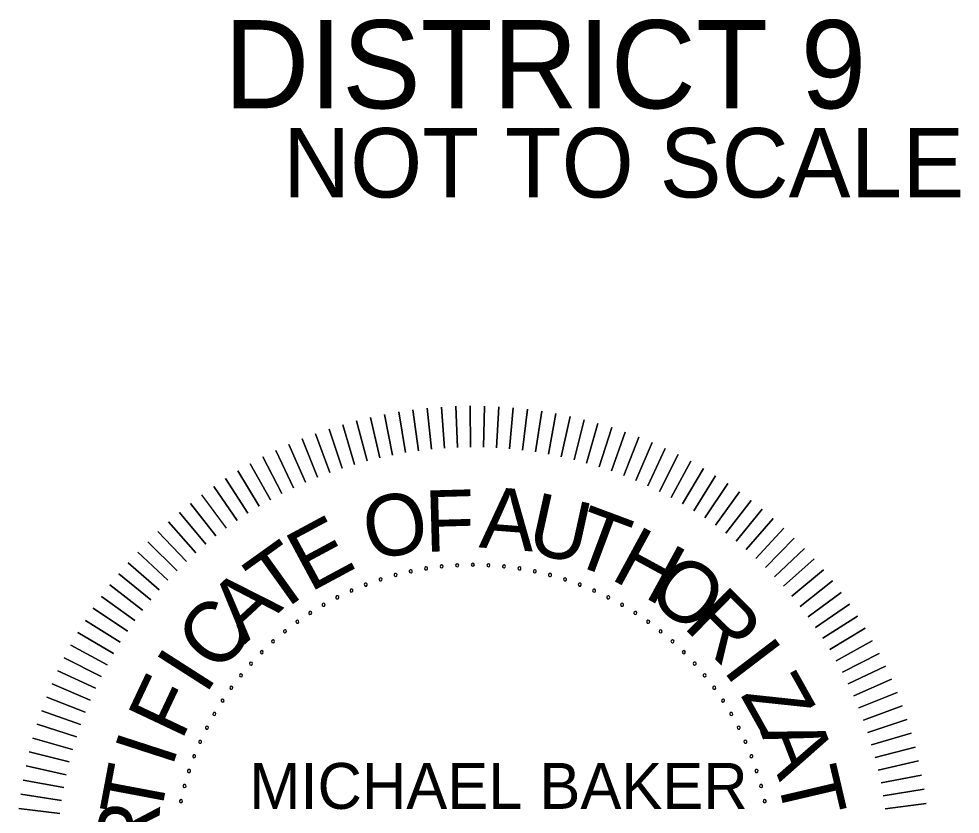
# Model space of a CAD drawing. Extents: x -13171 to 18763, y -8840 to 11152.
# Drawn here: x 10556 to 13118, y -7462 to -5298 of the extents above; entities that cross this region are included whole.
import ezdxf

# ---------------------------------------------------------------- set-up
doc = ezdxf.new("R2010")
doc.units = 0
for name, color, linetype in [('Level 2', 7, 'Continuous'), ('Level 47', 7, 'Continuous'), ('Level 48', 7, 'Continuous')]:
    doc.layers.add(name, color=color, linetype=linetype)

msp = doc.modelspace()

# ---------------------------------------------------------------- linework, layer by layer
at = {"layer": 'Level 47'}
for points in [[(11750, -6464.1), (11745.9, -6351.9)], [(11745.9, -6351.9), (11750, -6464.1)], [(11785.6, -6463.3), (11785, -6351.1)], [(11785, -6351.1), (11785.6, -6463.3)], [(11821.1, -6463.7), (11824, -6351.5)], [(11824, -6351.5), (11821.1, -6463.7)], [(11856.7, -6465.2), (11863.1, -6353.1)], [(11863.1, -6353.1), (11856.7, -6465.2)], [(11573.5, -6484.6), (11551.9, -6374.4)], [(11551.9, -6374.4), (11573.5, -6484.6)], [(11608.5, -6478.2), (11590.4, -6367.5)], [(11590.4, -6367.5), (11608.5, -6478.2)], [(11643.7, -6473), (11629, -6361.8)], [(11629, -6361.8), (11643.7, -6473)], [(11679.1, -6468.9), (11667.9, -6357.3)], [(11667.9, -6357.3), (11679.1, -6468.9)], [(11714.5, -6466), (11706.8, -6354)], [(11706.8, -6354), (11714.5, -6466)], [(11892.2, -6467.8), (11902.1, -6356)], [(11902.1, -6356), (11892.2, -6467.8)], [(11927.5, -6471.5), (11941, -6360)], [(11941, -6360), (11927.5, -6471.5)], [(11962.8, -6476.3), (11979.7, -6365.3)], [(11979.7, -6365.3), (11962.8, -6476.3)], [(11997.8, -6482.2), (12018.3, -6371.8)], [(12018.3, -6371.8), (11997.8, -6482.2)], [(11470, -6510), (11438.1, -6402.4)], [(11438.1, -6402.4), (11470, -6510)], [(11504.2, -6500.5), (11475.7, -6391.9)], [(11475.7, -6391.9), (11504.2, -6500.5)], [(11538.8, -6492), (11513.7, -6382.6)], [(11513.7, -6382.6), (11538.8, -6492)], [(12032.7, -6489.2), (12056.6, -6379.6)], [(12056.6, -6379.6), (12032.7, -6489.2)], [(12067.3, -6497.3), (12094.6, -6388.5)], [(12094.6, -6388.5), (12067.3, -6497.3)], [(12101.7, -6506.5), (12132.4, -6398.6)], [(12132.4, -6398.6), (12101.7, -6506.5)], [(11402.4, -6532.4), (11363.8, -6427)], [(11363.8, -6427), (11402.4, -6532.4)], [(11436, -6520.7), (11400.8, -6414.1)], [(11400.8, -6414.1), (11436, -6520.7)], [(12135.7, -6516.8), (12169.8, -6409.9)], [(12169.8, -6409.9), (12135.7, -6516.8)], [(12169.5, -6528.1), (12206.9, -6422.3)], [(12206.9, -6422.3), (12169.5, -6528.1)], [(11369.2, -6545.2), (11327.4, -6441)], [(11327.4, -6441), (11369.2, -6545.2)], [(12202.8, -6540.5), (12243.5, -6435.9)], [(12243.5, -6435.9), (12202.8, -6540.5)], [(12235.7, -6553.9), (12279.7, -6450.7)], [(12279.7, -6450.7), (12235.7, -6553.9)], [(11304.1, -6573.8), (11255.8, -6472.5)], [(11255.8, -6472.5), (11304.1, -6573.8)], [(11336.5, -6558.9), (11291.3, -6456.2)], [(11291.3, -6456.2), (11336.5, -6558.9)], [(12268.2, -6568.4), (12315.5, -6466.6)], [(12315.5, -6466.6), (12268.2, -6568.4)], [(11272.3, -6589.6), (11220.8, -6489.9)], [(11220.8, -6489.9), (11272.3, -6589.6)], [(12300.3, -6583.9), (12350.7, -6483.6)], [(12350.7, -6483.6), (12300.3, -6583.9)], [(12331.8, -6600.3), (12385.3, -6501.7)], [(12385.3, -6501.7), (12331.8, -6600.3)], [(11210.1, -6624.2), (11152.5, -6527.9)], [(11152.5, -6527.9), (11210.1, -6624.2)], [(11240.9, -6606.4), (11186.3, -6508.4)], [(11186.3, -6508.4), (11240.9, -6606.4)], [(12362.8, -6617.8), (12419.4, -6520.9)], [(12419.4, -6520.9), (12362.8, -6617.8)], [(11179.9, -6643), (11119.3, -6548.5)], [(11119.3, -6548.5), (11179.9, -6643)], [(12393.2, -6636.2), (12452.8, -6541.1)], [(12452.8, -6541.1), (12393.2, -6636.2)], [(11150.3, -6662.6), (11086.7, -6570.2)], [(11086.7, -6570.2), (11150.3, -6662.6)], [(12423, -6655.6), (12485.6, -6562.4)], [(12485.6, -6562.4), (12423, -6655.6)], [(11121.3, -6683.3), (11054.8, -6592.8)], [(12452.3, -6675.8), (12517.7, -6584.7)], [(12517.7, -6584.7), (12452.3, -6675.8)], [(12480.8, -6697), (12549.1, -6608)], [(12549.1, -6608), (12480.8, -6697)], [(11093, -6704.8), (11023.7, -6616.5)], [(11023.7, -6616.5), (11093, -6704.8)], [(12508.7, -6719.1), (12579.8, -6632.3)], [(12579.8, -6632.3), (12508.7, -6719.1)], [(11065.4, -6727.2), (10993.3, -6641.1)], [(10993.3, -6641.1), (11065.4, -6727.2)], [(12535.9, -6742.1), (12609.6, -6657.5)], [(12609.6, -6657.5), (12535.9, -6742.1)], [(11038.4, -6750.4), (10963.8, -6666.6)], [(10963.8, -6666.6), (11038.4, -6750.4)], [(12638.7, -6683.6), (12562.3, -6765.9)], [(12562.3, -6765.9), (12638.7, -6683.6)], [(11012.3, -6774.5), (10935, -6693.1)], [(10935, -6693.1), (11012.3, -6774.5)], [(12666.9, -6710.7), (12588, -6790.5)], [(12588, -6790.5), (12666.9, -6710.7)], [(10986.9, -6799.4), (10907.1, -6720.5)], [(10907.1, -6720.5), (10986.9, -6799.4)], [(10962.3, -6825.1), (10880, -6748.7)], [(10880, -6748.7), (10962.3, -6825.1)], [(12694.3, -6738.6), (12612.9, -6815.9)], [(12612.9, -6815.9), (12694.3, -6738.6)], [(10938.5, -6851.5), (10853.9, -6777.8)], [(10853.9, -6777.8), (10938.5, -6851.5)], [(12720.7, -6767.4), (12637, -6842)], [(12637, -6842), (12720.7, -6767.4)], [(10915.5, -6878.7), (10828.6, -6807.6)], [(10828.6, -6807.6), (10915.5, -6878.7)], [(12746.3, -6796.9), (12660.2, -6869)], [(12660.2, -6869), (12746.3, -6796.9)], [(10893.4, -6906.6), (10804.4, -6838.3)], [(10804.4, -6838.3), (10893.4, -6906.6)], [(12770.9, -6827.3), (12682.6, -6896.6)], [(12682.6, -6896.6), (12770.9, -6827.3)], [(12794.5, -6858.4), (12704.1, -6924.9)], [(12704.1, -6924.9), (12794.5, -6858.4)], [(10872.2, -6935.1), (10781.1, -6869.7)], [(10781.1, -6869.7), (10872.2, -6935.1)], [(12817.2, -6890.3), (12724.7, -6953.9)], [(12724.7, -6953.9), (12817.2, -6890.3)], [(10851.9, -6964.3), (10758.8, -6901.8)], [(10758.8, -6901.8), (10851.9, -6964.3)], [(10832.6, -6994.2), (10737.5, -6934.6)], [(10737.5, -6934.6), (10832.6, -6994.2)], [(12838.9, -6922.9), (12744.4, -6983.5)], [(12744.4, -6983.5), (12838.9, -6922.9)], [(10814.2, -7024.6), (10717.3, -6968)], [(10717.3, -6968), (10814.2, -7024.6)], [(12859.5, -6956.1), (12763.2, -7013.7)], [(12763.2, -7013.7), (12859.5, -6956.1)], [(12879, -6989.9), (12781, -7044.5)], [(12781, -7044.5), (12879, -6989.9)], [(10796.7, -7055.6), (10698.1, -7002.1)], [(10698.1, -7002.1), (10796.7, -7055.6)], [(10780.3, -7087.1), (10680, -7036.7)], [(10680, -7036.7), (10780.3, -7087.1)], [(12897.5, -7024.4), (12797.8, -7075.9)], [(12797.8, -7075.9), (12897.5, -7024.4)], [(12914.9, -7059.4), (12813.6, -7107.7)], [(12813.6, -7107.7), (12914.9, -7059.4)], [(10764.8, -7119.1), (10663, -7071.9)], [(10663, -7071.9), (10764.8, -7119.1)], [(12931.2, -7094.9), (12828.4, -7140.1)], [(12828.4, -7140.1), (12931.2, -7094.9)], [(10750.3, -7151.6), (10647.1, -7107.6)], [(10647.1, -7107.6), (10750.3, -7151.6)], [(10736.9, -7184.6), (10632.3, -7143.8)], [(10632.3, -7143.8), (10736.9, -7184.6)], [(12946.3, -7131), (12842.2, -7172.8)], [(12842.2, -7172.8), (12946.3, -7131)], [(12960.4, -7167.4), (12855, -7206)], [(12855, -7206), (12960.4, -7167.4)], [(10724.5, -7217.9), (10618.7, -7180.5)], [(10618.7, -7180.5), (10724.5, -7217.9)], [(10713.2, -7251.6), (10606.3, -7217.5)], [(10606.3, -7217.5), (10713.2, -7251.6)], [(12973.2, -7204.4), (12866.7, -7239.6)], [(12866.7, -7239.6), (12973.2, -7204.4)], [(12984.9, -7241.7), (12877.3, -7273.6)], [(12877.3, -7273.6), (12984.9, -7241.7)], [(10702.9, -7285.7), (10595, -7255)], [(10595, -7255), (10702.9, -7285.7)], [(10693.7, -7320), (10584.9, -7292.7)], [(10584.9, -7292.7), (10693.7, -7320)], [(12995.5, -7279.3), (12886.9, -7307.8)], [(12886.9, -7307.8), (12995.5, -7279.3)], [(13004.8, -7317.3), (12895.4, -7342.4)], [(12895.4, -7342.4), (13004.8, -7317.3)], [(10685.6, -7354.7), (10576, -7330.8)], [(10576, -7330.8), (10685.6, -7354.7)], [(10678.6, -7389.5), (10568.2, -7369.1)], [(10568.2, -7369.1), (10678.6, -7389.5)], [(13012.9, -7355.5), (12902.8, -7377.1)], [(12902.8, -7377.1), (13012.9, -7355.5)], [(13019.9, -7394), (12909.1, -7412.2)], [(12909.1, -7412.2), (13019.9, -7394)], [(10672.7, -7424.6), (10561.7, -7407.7)], [(10561.7, -7407.7), (10672.7, -7424.6)], [(10667.9, -7459.9), (10556.4, -7446.4)], [(10556.4, -7446.4), (10667.9, -7459.9)], [(13025.6, -7432.6), (12914.3, -7447.3)], [(12914.3, -7447.3), (13025.6, -7432.6)]]:
    msp.add_lwpolyline(points, dxfattribs=at)
for centre, start, end in [((11707, -6787.8), 6, 186), ((11707, -6787.8), 186, 6), ((11749.4, -6784.5), 3, 183), ((11749.4, -6784.5), 183, 3), ((11791.9, -6783.3), 0, 180), ((11791.9, -6783.3), 180, 0), ((11834.4, -6784.5), 357, 177), ((11834.4, -6784.5), 177, 357), ((11876.8, -6787.8), 354, 174), ((11876.8, -6787.8), 174, 354), ((11581.7, -6811), 15, 195), ((11581.7, -6811), 195, 15), ((11623, -6801.1), 12, 192), ((11623, -6801.1), 192, 12), ((11664.8, -6793.3), 9, 189), ((11664.8, -6793.3), 189, 9), ((11918.9, -6793.3), 351, 171), ((11918.9, -6793.3), 171, 351), ((11960.7, -6801.1), 168, 348), ((11960.7, -6801.1), 348, 168), ((12002.1, -6811), 165, 345), ((12002.1, -6811), 345, 165), ((11500.8, -6837.3), 21, 201), ((11500.8, -6837.3), 201, 21), ((11540.9, -6823.1), 18, 198), ((11540.9, -6823.1), 198, 18), ((12042.9, -6823.1), 162, 342), ((12042.9, -6823.1), 342, 162), ((12082.9, -6837.3), 159, 339), ((12082.9, -6837.3), 339, 159), ((11461.6, -6853.6), 24, 204), ((11461.6, -6853.6), 204, 24), ((12122.2, -6853.6), 156, 336), ((12122.2, -6853.6), 336, 156), ((11385.8, -6892.2), 30, 210), ((11385.8, -6892.2), 210, 30), ((11423.2, -6871.9), 27, 207), ((11423.2, -6871.9), 207, 27), ((12160.6, -6871.9), 153, 333), ((12160.6, -6871.9), 333, 153), ((12198, -6892.2), 150, 330), ((12198, -6892.2), 330, 150), ((11349.6, -6914.4), 33, 213), ((11349.6, -6914.4), 213, 33), ((12234.2, -6914.4), 147, 327), ((12234.2, -6914.4), 327, 147), ((11314.5, -6938.5), 36, 216), ((11314.5, -6938.5), 216, 36), ((12269.3, -6938.5), 144, 324), ((12269.3, -6938.5), 324, 144), ((11280.8, -6964.3), 39, 219), ((11280.8, -6964.3), 219, 39), ((12303, -6964.3), 141, 321), ((12303, -6964.3), 321, 141), ((11248.5, -6991.9), 42, 222), ((11248.5, -6991.9), 222, 42), ((12335.3, -6991.9), 138, 318), ((12335.3, -6991.9), 318, 138), ((11217.6, -7021.2), 45, 225), ((11217.6, -7021.2), 225, 45), ((12366.2, -7021.2), 135, 315), ((12366.2, -7021.2), 315, 135), ((11188.3, -7052.1), 48, 228), ((11188.3, -7052.1), 228, 48), ((12395.4, -7052.1), 132, 312), ((12395.4, -7052.1), 312, 132), ((11160.7, -7084.4), 51, 231), ((11160.7, -7084.4), 231, 51), ((12423, -7084.4), 129, 309), ((12423, -7084.4), 309, 129), ((11134.8, -7118.1), 54, 234), ((11134.8, -7118.1), 234, 54), ((12448.9, -7118.1), 126, 306), ((12448.9, -7118.1), 306, 126), ((11110.8, -7153.2), 57, 237), ((11110.8, -7153.2), 237, 57), ((12473, -7153.2), 123, 303), ((12473, -7153.2), 303, 123), ((11088.5, -7189.4), 60, 240), ((11088.5, -7189.4), 240, 60), ((12495.2, -7189.4), 120, 300), ((12495.2, -7189.4), 300, 120), ((11068.3, -7226.8), 63, 243), ((11068.3, -7226.8), 243, 63), ((12515.5, -7226.8), 117, 297), ((12515.5, -7226.8), 297, 117), ((11050, -7265.2), 66, 246), ((11050, -7265.2), 246, 66), ((12533.8, -7265.2), 114, 294), ((12533.8, -7265.2), 294, 114), ((11033.7, -7304.4), 69, 249), ((11033.7, -7304.4), 249, 69), ((12550.1, -7304.4), 111, 291), ((12550.1, -7304.4), 291, 111), ((11019.5, -7344.5), 72, 252), ((11019.5, -7344.5), 252, 72), ((12564.3, -7344.5), 108, 288), ((12564.3, -7344.5), 288, 108), ((11007.4, -7385.3), 75, 255), ((11007.4, -7385.3), 255, 75), ((12576.4, -7385.3), 105, 285), ((12576.4, -7385.3), 285, 105), ((10997.5, -7426.6), 78, 258), ((10997.5, -7426.6), 258, 78), ((12586.3, -7426.6), 102, 282), ((12586.3, -7426.6), 282, 102)]:
    msp.add_arc(centre, 4.17, start, end, dxfattribs=at)

# ---------------------------------------------------------------- texts
at = {"layer": 'Level 2'}
msp.add_text('NOT TO SCALE', height=189, dxfattribs=at).set_placement((11275.4, -5783.8))
at = {"layer": 'Level 47'}
for s, rotation, p in [('F', 1.5867, (11662.6, -6748.2)), ('A', 355.5955, (11807.1, -6735.9)), ('O', 10.7295, (11510.3, -6772.2)), ('U', 347.5481, (11933.2, -6747.8)), ('T', 339.5007, (12049.5, -6775.6)), ('E', 28.279, (11348.5, -6859.6)), ('H', 331.4533, (12162.6, -6820.2)), ('T', 35.5725, (11255.4, -6924.1)), ('O', 323.4059, (12258.3, -6872.9)), ('A', 42.8659, (11170.8, -7001.1)), ('R', 315.3585, (12361.5, -6951.9)), ('C', 50.1594, (11100.6, -7084.4)), ('I', 307.3112, (12469.9, -7069.3)), ('I', 57.4529, (11064.4, -7140.1)), ('Z', 299.2638, (12518.8, -7137.2)), ('F', 64.7464, (10999, -7264.8)), ('I', 72.0398, (10973.2, -7338)), ('A', 291.2164, (12573.5, -7237.5)), ('T', 79.3333, (10940.1, -7481.6)), ('T', 283.169, (12617.1, -7355.4)), ('R', 86.6268, (10932.4, -7591.8))]:
    msp.add_text(s, height=166.7, rotation=rotation, dxfattribs=at).set_placement(p)
msp.add_text('MICHAEL BAKER', height=125.016, dxfattribs=at).set_placement((11183.6, -7447.7))
at = {"layer": 'Level 48'}
msp.add_text('DISTRICT 9', height=240, dxfattribs=at).set_placement((11115.2, -5541.2))

doc.saveas('drawing.dxf')
